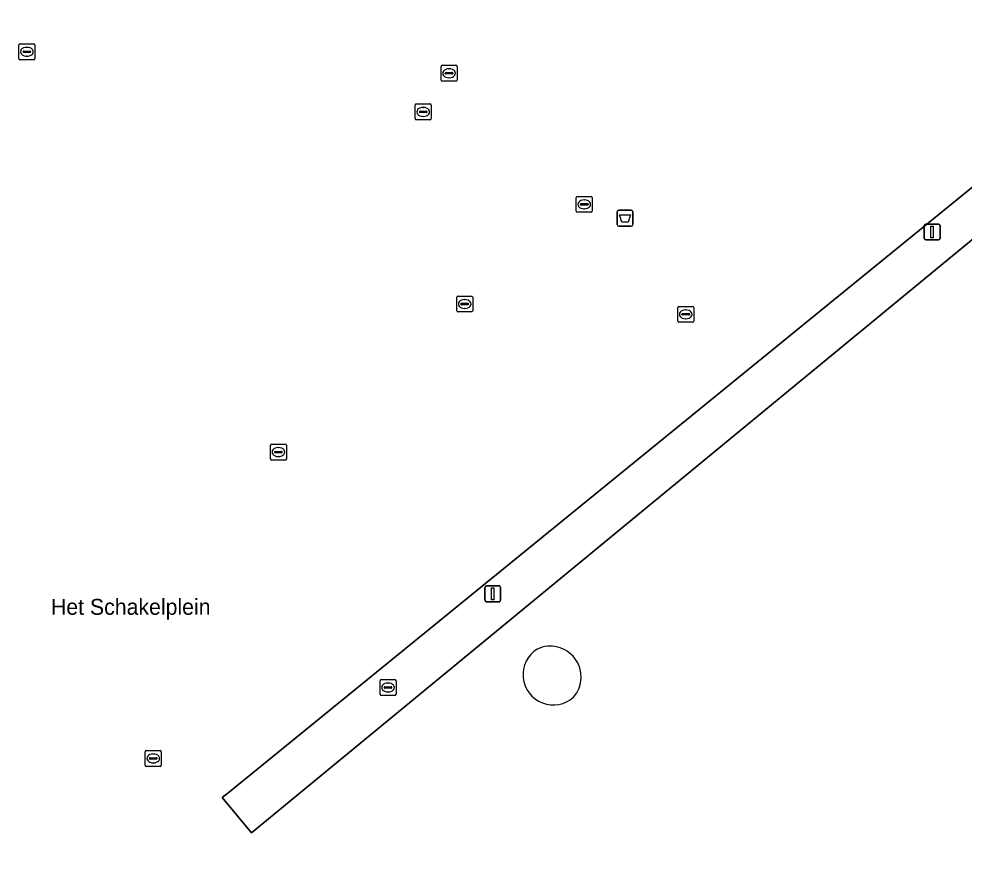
# Model space of a CAD drawing. Extents: x 156141 to 158132, y 385651 to 388333.
# Drawn here: x 157148.7 to 157208.1, y 386251.8 to 386304.4 of the extents above; entities that cross this region are included whole.
import ezdxf

# ---------------------------------------------------------------- set-up
doc = ezdxf.new("R2010")
doc.units = 0
for name, color, linetype in [('IMGEO_Afvalbak', 7, 'Continuous'), ('IMGEO_Brandkraan', 7, 'Continuous'), ('IMGEO_Erf', 7, 'Continuous'), ('IMGEO_Groenvoorziening', 7, 'Continuous'), ('IMGEO_Haag', 7, 'Continuous'), ('IMGEO_Hek', 7, 'Continuous'), ('IMGEO_Kolk', 7, 'Continuous'), ('IMGEO_Lichtmast', 7, 'Continuous'), ('IMGEO_Openbare_ruimte_label', 7, 'Continuous'), ('IMGEO_Opslagtank', 7, 'Continuous'), ('IMGEO_Rioolput', 7, 'Continuous')]:
    doc.layers.add(name, color=color, linetype=linetype)

msp = doc.modelspace()

# ---------------------------------------------------------------- linework, layer by layer
at = {"layer": 'IMGEO_Afvalbak'}
for p, q in [((157186.268, 386291.448), (157186.268, 386292.248)), ((157186.268, 386292.248), (157186.268, 386291.448)), ((157186.368, 386292.348), (157187.158, 386292.348)), ((157187.158, 386292.348), (157186.368, 386292.348)), ((157187.258, 386292.248), (157187.258, 386291.448)), ((157187.258, 386291.448), (157187.258, 386292.248)), ((157187.158, 386291.348), (157186.368, 386291.348)), ((157186.368, 386291.348), (157187.158, 386291.348))]:
    msp.add_line(p, q, dxfattribs=at)
msp.add_lwpolyline([(157186.411, 386292.062), (157187.115, 386292.062), (157186.966, 386291.592), (157186.56, 386291.592), (157186.411, 386292.062)], dxfattribs=at)
for centre, start, end in [((157186.368, 386292.248), 90, 180), ((157186.368, 386292.248), 90, 180), ((157187.158, 386292.248), 0, 90), ((157187.158, 386292.248), 360, 90), ((157186.368, 386291.448), 180, 270), ((157186.368, 386291.448), 180, 270), ((157187.158, 386291.448), 270, 0), ((157187.158, 386291.448), 270, 0)]:
    msp.add_arc(centre, 0.1, start, end, dxfattribs=at)
at = {"layer": 'IMGEO_Brandkraan'}
for p, q in [((157171.364, 386261.91), (157171.364, 386262.762)), ((157171.439, 386262.836), (157172.291, 386262.836)), ((157172.365, 386262.762), (157172.365, 386261.91)), ((157171.623, 386262.33), (157171.623, 386262.342)), ((157172.061, 386262.293), (157171.663, 386262.293)), ((157171.666, 386262.379), (157172.064, 386262.379)), ((157171.852, 386262.616), (157171.877, 386262.616)), ((157172.107, 386262.342), (157172.107, 386262.33)), ((157172.291, 386261.836), (157171.439, 386261.836)), ((157171.875, 386262.056), (157171.85, 386262.056))]:
    msp.add_line(p, q, dxfattribs=at)
for points in [[(157171.364, 386261.91), (157171.364, 386262.762)], [(157171.439, 386262.836), (157172.291, 386262.836)], [(157172.365, 386262.762), (157172.365, 386261.91)], [(157172.291, 386261.836), (157171.439, 386261.836)]]:
    msp.add_lwpolyline(points, dxfattribs=at)
for centre, radius, start, end in [((157171.441, 386262.76), 0.0765, 91.55205, 178.44795), ((157171.441, 386262.76), 0.0765, 91.55205, 178.44795), ((157172.289, 386262.76), 0.0765, 1.55205, 88.44795), ((157172.289, 386262.76), 0.0765, 1.55205, 88.44795), ((157171.663, 386262.339), 0.0403, 85.87752, 175.75265), ((157171.66, 386262.329), 0.0366, 178.93798, 274.71019), ((157172.064, 386262.336), 0.043, 264.86636, 352.45326), ((157172.068, 386262.341), 0.0386, 1.73085, 96.63898), ((157171.441, 386261.912), 0.0765, 181.55205, 268.44795), ((157171.441, 386261.912), 0.0765, 181.55205, 268.44795), ((157172.289, 386261.912), 0.0765, 271.55205, 358.44795), ((157172.289, 386261.912), 0.0765, 271.55205, 358.44795)]:
    msp.add_arc(centre, radius, start, end, dxfattribs=at)
for centre, major_axis, ratio, start_param, end_param in [((157171.851, 386262.336), (-0.387, 0.002), 0.722429, 4.712389, 7.853982), ((157171.876, 386262.336), (-0.39, 0.002), 0.717154, 1.570796, 4.712389)]:
    msp.add_ellipse(centre, major_axis=major_axis, ratio=ratio, start_param=start_param, end_param=end_param, dxfattribs=at)
at = {"layer": 'IMGEO_Erf'}
msp.add_lwpolyline([(157213.671, 386179.31), (157318.008, 386237.675), (157310.24, 386250.894), (157308.881, 386253.009), (157305.737, 386257.034), (157297.068, 386267.539), (157250.016, 386324.597), (157249.125, 386323.863), (157233.385, 386310.904), (157232.673, 386310.318), (157226.757, 386305.447), (157227.019, 386305.124), (157227.309, 386305.361), (157228.122, 386304.37), (157229.365, 386302.857), (157226.965, 386300.89), (157224.909, 386303.4), (157225.394, 386303.796), (157225.13, 386304.108), (157163.286, 386253.19), (157161.441, 386255.415), (157161.905, 386255.778), (157223.541, 386305.983)], dxfattribs=at)
for centre, radius, start, end in [((157182.258, 386263.144), 1.905, 122.28651, 311.91208), ((157182.063, 386262.996), 1.941, 319.10904, 115.08956)]:
    msp.add_arc(centre, radius, start, end, dxfattribs=at)
at = {"layer": 'IMGEO_Groenvoorziening'}
msp.add_lwpolyline([(157223.541, 386305.983), (157161.905, 386255.778), (157161.441, 386255.415), (157163.286, 386253.19), (157225.13, 386304.108)], close=True, dxfattribs=at)
at = {"layer": 'IMGEO_Haag'}
msp.add_lwpolyline([(157223.541, 386305.983), (157161.905, 386255.778), (157161.441, 386255.415), (157163.286, 386253.19), (157225.13, 386304.108)], close=True, dxfattribs=at)
at = {"layer": 'IMGEO_Hek'}
msp.add_lwpolyline([(157225.13, 386304.108), (157163.286, 386253.19)], dxfattribs=at)
at = {"layer": 'IMGEO_Kolk'}
for p, q in [((157148.656, 386301.888), (157148.656, 386302.74)), ((157148.731, 386302.814), (157149.583, 386302.814)), ((157149.144, 386302.594), (157149.169, 386302.594)), ((157149.657, 386302.74), (157149.657, 386301.888)), ((157148.915, 386302.308), (157148.915, 386302.32)), ((157149.353, 386302.271), (157148.955, 386302.271)), ((157148.958, 386302.357), (157149.356, 386302.357)), ((157149.167, 386302.034), (157149.142, 386302.034)), ((157149.399, 386302.32), (157149.399, 386302.308)), ((157149.583, 386301.814), (157148.731, 386301.814)), ((157183.698, 386292.294), (157183.698, 386293.146)), ((157183.773, 386293.22), (157184.625, 386293.22)), ((157184.699, 386293.146), (157184.699, 386292.294)), ((157183.957, 386292.714), (157183.957, 386292.726)), ((157184.395, 386292.677), (157183.997, 386292.677)), ((157184, 386292.763), (157184.398, 386292.763)), ((157184.209, 386292.44), (157184.184, 386292.44)), ((157184.186, 386293), (157184.211, 386293)), ((157184.441, 386292.726), (157184.441, 386292.714)), ((157184.625, 386292.22), (157183.773, 386292.22)), ((157176.184, 386286.026), (157176.184, 386286.878)), ((157176.259, 386286.952), (157177.111, 386286.952)), ((157176.486, 386286.495), (157176.884, 386286.495)), ((157176.672, 386286.732), (157176.697, 386286.732)), ((157177.185, 386286.878), (157177.185, 386286.026)), ((157177.111, 386285.952), (157176.259, 386285.952)), ((157176.443, 386286.446), (157176.443, 386286.458)), ((157176.881, 386286.409), (157176.483, 386286.409)), ((157176.695, 386286.172), (157176.67, 386286.172)), ((157176.927, 386286.458), (157176.927, 386286.446)), ((157164.474, 386276.713), (157164.474, 386277.565)), ((157164.549, 386277.639), (157165.401, 386277.639)), ((157165.475, 386277.565), (157165.475, 386276.713)), ((157164.733, 386277.133), (157164.733, 386277.145)), ((157165.171, 386277.096), (157164.773, 386277.096)), ((157164.776, 386277.182), (157165.174, 386277.182)), ((157164.962, 386277.419), (157164.987, 386277.419)), ((157165.217, 386277.145), (157165.217, 386277.133)), ((157165.401, 386276.639), (157164.549, 386276.639)), ((157164.985, 386276.859), (157164.96, 386276.859))]:
    msp.add_line(p, q, dxfattribs=at)
for points in [[(157148.656, 386301.888), (157148.656, 386302.74)], [(157148.731, 386302.814), (157149.583, 386302.814)], [(157149.657, 386302.74), (157149.657, 386301.888)], [(157149.583, 386301.814), (157148.731, 386301.814)], [(157183.698, 386292.294), (157183.698, 386293.146)], [(157183.773, 386293.22), (157184.625, 386293.22)], [(157184.699, 386293.146), (157184.699, 386292.294)], [(157184.625, 386292.22), (157183.773, 386292.22)], [(157176.184, 386286.026), (157176.184, 386286.878)], [(157176.259, 386286.952), (157177.111, 386286.952)], [(157177.185, 386286.878), (157177.185, 386286.026)], [(157177.111, 386285.952), (157176.259, 386285.952)], [(157164.474, 386276.713), (157164.474, 386277.565)], [(157164.549, 386277.639), (157165.401, 386277.639)], [(157165.475, 386277.565), (157165.475, 386276.713)], [(157165.401, 386276.639), (157164.549, 386276.639)]]:
    msp.add_lwpolyline(points, dxfattribs=at)
for centre, radius, start, end in [((157148.733, 386302.738), 0.0765, 91.55205, 178.44795), ((157148.733, 386302.738), 0.0765, 91.55205, 178.44795), ((157149.581, 386302.738), 0.0765, 1.55205, 88.44795), ((157149.581, 386302.738), 0.0765, 1.55205, 88.44795), ((157148.955, 386302.317), 0.0403, 85.87752, 175.75265), ((157148.952, 386302.307), 0.0366, 178.93798, 274.71019), ((157149.356, 386302.314), 0.043, 264.86636, 352.45326), ((157149.36, 386302.319), 0.0386, 1.73085, 96.63898), ((157148.733, 386301.89), 0.0765, 181.55205, 268.44795), ((157148.733, 386301.89), 0.0765, 181.55205, 268.44795), ((157149.581, 386301.89), 0.0765, 271.55205, 358.44795), ((157149.581, 386301.89), 0.0765, 271.55205, 358.44795), ((157183.775, 386293.144), 0.0765, 91.55205, 178.44795), ((157183.775, 386293.144), 0.0765, 91.55205, 178.44795), ((157184.623, 386293.144), 0.0765, 1.55205, 88.44795), ((157184.623, 386293.144), 0.0765, 1.55205, 88.44795), ((157183.997, 386292.723), 0.0403, 85.87752, 175.75265), ((157183.994, 386292.713), 0.0366, 178.93798, 274.71019), ((157184.398, 386292.72), 0.043, 264.86636, 352.45326), ((157184.402, 386292.725), 0.0386, 1.73085, 96.63898), ((157183.775, 386292.296), 0.0765, 181.55205, 268.44795), ((157183.775, 386292.296), 0.0765, 181.55205, 268.44795), ((157184.623, 386292.296), 0.0765, 271.55205, 358.44795), ((157184.623, 386292.296), 0.0765, 271.55205, 358.44795), ((157176.261, 386286.876), 0.0765, 91.55205, 178.44795), ((157176.261, 386286.876), 0.0765, 91.55205, 178.44795), ((157176.483, 386286.455), 0.0403, 85.87752, 175.75265), ((157176.888, 386286.457), 0.0386, 1.73085, 96.63898), ((157177.109, 386286.876), 0.0765, 1.55205, 88.44795), ((157177.109, 386286.876), 0.0765, 1.55205, 88.44795), ((157176.261, 386286.028), 0.0765, 181.55205, 268.44795), ((157176.261, 386286.028), 0.0765, 181.55205, 268.44795), ((157176.48, 386286.445), 0.0366, 178.93798, 274.71019), ((157176.884, 386286.452), 0.043, 264.86636, 352.45326), ((157177.109, 386286.028), 0.0765, 271.55205, 358.44795), ((157177.109, 386286.028), 0.0765, 271.55205, 358.44795), ((157164.551, 386277.563), 0.0765, 91.55205, 178.44795), ((157164.551, 386277.563), 0.0765, 91.55205, 178.44795), ((157165.399, 386277.563), 0.0765, 1.55205, 88.44795), ((157165.399, 386277.563), 0.0765, 1.55205, 88.44795), ((157164.773, 386277.142), 0.0403, 85.87752, 175.75265), ((157164.77, 386277.132), 0.0366, 178.93798, 274.71019), ((157165.174, 386277.139), 0.043, 264.86636, 352.45326), ((157165.178, 386277.144), 0.0386, 1.73085, 96.63898), ((157164.551, 386276.715), 0.0765, 181.55205, 268.44795), ((157164.551, 386276.715), 0.0765, 181.55205, 268.44795), ((157165.399, 386276.715), 0.0765, 271.55205, 358.44795), ((157165.399, 386276.715), 0.0765, 271.55205, 358.44795)]:
    msp.add_arc(centre, radius, start, end, dxfattribs=at)
for centre, major_axis, ratio, start_param, end_param in [((157149.143, 386302.314), (-0.387, 0.002), 0.722429, 4.712389, 7.853982), ((157149.168, 386302.314), (-0.39, 0.002), 0.717154, 1.570796, 4.712389), ((157184.185, 386292.72), (-0.387, 0.002), 0.722429, 4.712389, 7.853982), ((157184.21, 386292.72), (-0.39, 0.002), 0.717154, 1.570796, 4.712389), ((157176.671, 386286.452), (-0.387, 0.002), 0.722429, 4.712389, 7.853982), ((157176.696, 386286.452), (-0.39, 0.002), 0.717154, 1.570796, 4.712389), ((157164.961, 386277.139), (-0.387, 0.002), 0.722429, 4.712389, 7.853982), ((157164.986, 386277.139), (-0.39, 0.002), 0.717154, 1.570796, 4.712389)]:
    msp.add_ellipse(centre, major_axis=major_axis, ratio=ratio, start_param=start_param, end_param=end_param, dxfattribs=at)
at = {"layer": 'IMGEO_Lichtmast'}
for p, q in [((157205.577, 386290.58), (157205.577, 386291.38)), ((157205.577, 386291.38), (157205.577, 386290.58)), ((157205.677, 386291.48), (157206.467, 386291.48)), ((157206.467, 386291.48), (157205.677, 386291.48)), ((157206.567, 386291.38), (157206.567, 386290.58)), ((157206.567, 386290.58), (157206.567, 386291.38)), ((157206.467, 386290.48), (157205.677, 386290.48)), ((157205.677, 386290.48), (157206.467, 386290.48)), ((157178.052, 386268.726), (157178.842, 386268.726)), ((157178.842, 386268.726), (157178.052, 386268.726)), ((157177.952, 386267.826), (157177.952, 386268.626)), ((157177.952, 386268.626), (157177.952, 386267.826)), ((157178.942, 386268.626), (157178.942, 386267.826)), ((157178.942, 386267.826), (157178.942, 386268.626)), ((157178.842, 386267.726), (157178.052, 386267.726)), ((157178.052, 386267.726), (157178.842, 386267.726))]:
    msp.add_line(p, q, dxfattribs=at)
for points in [[(157205.997, 386291.355), (157206.147, 386291.355), (157206.147, 386290.605), (157205.997, 386290.605), (157205.997, 386291.355)], [(157178.372, 386268.601), (157178.522, 386268.601), (157178.522, 386267.851), (157178.372, 386267.851), (157178.372, 386268.601)]]:
    msp.add_lwpolyline(points, dxfattribs=at)
for centre, start, end in [((157205.677, 386291.38), 90, 180), ((157205.677, 386291.38), 90, 180), ((157206.467, 386291.38), 0, 90), ((157206.467, 386291.38), 360, 90), ((157205.677, 386290.58), 180, 270), ((157205.677, 386290.58), 180, 270), ((157206.467, 386290.58), 270, 0), ((157206.467, 386290.58), 270, 0), ((157178.052, 386268.626), 90, 180), ((157178.052, 386268.626), 90, 180), ((157178.842, 386268.626), 0, 90), ((157178.842, 386268.626), 360, 90), ((157178.052, 386267.826), 180, 270), ((157178.052, 386267.826), 180, 270), ((157178.842, 386267.826), 270, 0), ((157178.842, 386267.826), 270, 0)]:
    msp.add_arc(centre, 0.1, start, end, dxfattribs=at)
at = {"layer": 'IMGEO_Opslagtank'}
for centre, radius, start, end in [((157182.258, 386263.144), 1.905, 122.28651, 311.91208), ((157182.063, 386262.996), 1.941, 319.10904, 115.08956)]:
    msp.add_arc(centre, radius, start, end, dxfattribs=at)
at = {"layer": 'IMGEO_Rioolput'}
for p, q in [((157175.204, 386300.537), (157175.204, 386301.389)), ((157175.279, 386301.463), (157176.131, 386301.463)), ((157176.205, 386301.389), (157176.205, 386300.537)), ((157175.463, 386300.957), (157175.463, 386300.969)), ((157175.901, 386300.92), (157175.503, 386300.92)), ((157175.506, 386301.006), (157175.904, 386301.006)), ((157175.692, 386301.243), (157175.717, 386301.243)), ((157175.947, 386300.969), (157175.947, 386300.957)), ((157176.131, 386300.463), (157175.279, 386300.463)), ((157175.715, 386300.683), (157175.69, 386300.683)), ((157173.574, 386298.108), (157173.574, 386298.96)), ((157173.649, 386299.034), (157174.501, 386299.034)), ((157174.575, 386298.96), (157174.575, 386298.108)), ((157173.833, 386298.528), (157173.833, 386298.54)), ((157174.271, 386298.491), (157173.873, 386298.491)), ((157173.876, 386298.577), (157174.274, 386298.577)), ((157174.062, 386298.814), (157174.087, 386298.814)), ((157174.317, 386298.54), (157174.317, 386298.528)), ((157174.501, 386298.034), (157173.649, 386298.034)), ((157174.085, 386298.254), (157174.06, 386298.254)), ((157190.081, 386285.379), (157190.081, 386286.231)), ((157190.156, 386286.305), (157191.008, 386286.305)), ((157190.569, 386286.085), (157190.594, 386286.085)), ((157191.082, 386286.231), (157191.082, 386285.379)), ((157191.008, 386285.305), (157190.156, 386285.305)), ((157190.34, 386285.799), (157190.34, 386285.811)), ((157190.778, 386285.762), (157190.38, 386285.762)), ((157190.383, 386285.848), (157190.781, 386285.848)), ((157190.592, 386285.525), (157190.567, 386285.525)), ((157190.824, 386285.811), (157190.824, 386285.799)), ((157156.602, 386257.448), (157156.602, 386258.3)), ((157156.677, 386258.374), (157157.529, 386258.374)), ((157157.09, 386258.154), (157157.115, 386258.154)), ((157157.603, 386258.3), (157157.603, 386257.448)), ((157157.529, 386257.374), (157156.677, 386257.374)), ((157156.861, 386257.868), (157156.861, 386257.88)), ((157157.299, 386257.831), (157156.901, 386257.831)), ((157156.904, 386257.917), (157157.302, 386257.917)), ((157157.113, 386257.594), (157157.088, 386257.594)), ((157157.345, 386257.88), (157157.345, 386257.868))]:
    msp.add_line(p, q, dxfattribs=at)
for points in [[(157175.204, 386300.537), (157175.204, 386301.389)], [(157175.279, 386301.463), (157176.131, 386301.463)], [(157176.205, 386301.389), (157176.205, 386300.537)], [(157176.131, 386300.463), (157175.279, 386300.463)], [(157173.574, 386298.108), (157173.574, 386298.96)], [(157173.649, 386299.034), (157174.501, 386299.034)], [(157174.575, 386298.96), (157174.575, 386298.108)], [(157174.501, 386298.034), (157173.649, 386298.034)], [(157190.081, 386285.379), (157190.081, 386286.231)], [(157190.156, 386286.305), (157191.008, 386286.305)], [(157191.082, 386286.231), (157191.082, 386285.379)], [(157191.008, 386285.305), (157190.156, 386285.305)], [(157156.602, 386257.448), (157156.602, 386258.3)], [(157156.677, 386258.374), (157157.529, 386258.374)], [(157157.603, 386258.3), (157157.603, 386257.448)], [(157157.529, 386257.374), (157156.677, 386257.374)]]:
    msp.add_lwpolyline(points, dxfattribs=at)
for centre, radius, start, end in [((157175.281, 386301.387), 0.0765, 91.55205, 178.44795), ((157175.281, 386301.387), 0.0765, 91.55205, 178.44795), ((157176.129, 386301.387), 0.0765, 1.55205, 88.44795), ((157176.129, 386301.387), 0.0765, 1.55205, 88.44795), ((157175.503, 386300.966), 0.0403, 85.87752, 175.75265), ((157175.5, 386300.956), 0.0366, 178.93798, 274.71019), ((157175.904, 386300.963), 0.043, 264.86636, 352.45326), ((157175.908, 386300.968), 0.0386, 1.73085, 96.63898), ((157175.281, 386300.539), 0.0765, 181.55205, 268.44795), ((157175.281, 386300.539), 0.0765, 181.55205, 268.44795), ((157176.129, 386300.539), 0.0765, 271.55205, 358.44795), ((157176.129, 386300.539), 0.0765, 271.55205, 358.44795), ((157173.651, 386298.958), 0.0765, 91.55205, 178.44795), ((157173.651, 386298.958), 0.0765, 91.55205, 178.44795), ((157174.499, 386298.958), 0.0765, 1.55205, 88.44795), ((157174.499, 386298.958), 0.0765, 1.55205, 88.44795), ((157173.873, 386298.537), 0.0403, 85.87752, 175.75265), ((157173.87, 386298.527), 0.0366, 178.93798, 274.71019), ((157174.274, 386298.534), 0.043, 264.86636, 352.45326), ((157174.278, 386298.539), 0.0386, 1.73085, 96.63898), ((157173.651, 386298.11), 0.0765, 181.55205, 268.44795), ((157173.651, 386298.11), 0.0765, 181.55205, 268.44795), ((157174.499, 386298.11), 0.0765, 271.55205, 358.44795), ((157174.499, 386298.11), 0.0765, 271.55205, 358.44795), ((157190.158, 386286.229), 0.0765, 91.55205, 178.44795), ((157190.158, 386286.229), 0.0765, 91.55205, 178.44795), ((157191.006, 386286.229), 0.0765, 1.55205, 88.44795), ((157191.006, 386286.229), 0.0765, 1.55205, 88.44795), ((157190.158, 386285.381), 0.0765, 181.55205, 268.44795), ((157190.158, 386285.381), 0.0765, 181.55205, 268.44795), ((157190.38, 386285.808), 0.0403, 85.87752, 175.75265), ((157190.377, 386285.798), 0.0366, 178.93798, 274.71019), ((157190.781, 386285.805), 0.043, 264.86636, 352.45326), ((157190.785, 386285.81), 0.0386, 1.73085, 96.63898), ((157191.006, 386285.381), 0.0765, 271.55205, 358.44795), ((157191.006, 386285.381), 0.0765, 271.55205, 358.44795), ((157156.679, 386258.298), 0.0765, 91.55205, 178.44795), ((157156.679, 386258.298), 0.0765, 91.55205, 178.44795), ((157157.527, 386258.298), 0.0765, 1.55205, 88.44795), ((157157.527, 386258.298), 0.0765, 1.55205, 88.44795), ((157156.679, 386257.45), 0.0765, 181.55205, 268.44795), ((157156.679, 386257.45), 0.0765, 181.55205, 268.44795), ((157156.901, 386257.877), 0.0403, 85.87752, 175.75265), ((157156.898, 386257.867), 0.0366, 178.93798, 274.71019), ((157157.302, 386257.874), 0.043, 264.86636, 352.45326), ((157157.306, 386257.879), 0.0386, 1.73085, 96.63898), ((157157.527, 386257.45), 0.0765, 271.55205, 358.44795), ((157157.527, 386257.45), 0.0765, 271.55205, 358.44795)]:
    msp.add_arc(centre, radius, start, end, dxfattribs=at)
for centre, major_axis, ratio, start_param, end_param in [((157175.691, 386300.963), (-0.387, 0.002), 0.722429, 4.712389, 7.853982), ((157175.716, 386300.963), (-0.39, 0.002), 0.717154, 1.570796, 4.712389), ((157174.061, 386298.534), (-0.387, 0.002), 0.722429, 4.712389, 7.853982), ((157174.086, 386298.534), (-0.39, 0.002), 0.717154, 1.570796, 4.712389), ((157190.568, 386285.805), (-0.387, 0.002), 0.722429, 4.712389, 7.853982), ((157190.593, 386285.805), (-0.39, 0.002), 0.717154, 1.570796, 4.712389), ((157157.089, 386257.874), (-0.387, 0.002), 0.722429, 4.712389, 7.853982), ((157157.114, 386257.874), (-0.39, 0.002), 0.717154, 1.570796, 4.712389)]:
    msp.add_ellipse(centre, major_axis=major_axis, ratio=ratio, start_param=start_param, end_param=end_param, dxfattribs=at)

# ---------------------------------------------------------------- texts
at = {"layer": 'IMGEO_Openbare_ruimte_label'}
msp.add_text('Het Schakelplein', height=1, dxfattribs=at).set_placement((157150.67, 386266.908))

doc.saveas('drawing.dxf')
